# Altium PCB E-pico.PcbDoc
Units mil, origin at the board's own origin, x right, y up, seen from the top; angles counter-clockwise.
Board outline 2065 x 820 mil, 2 copper layers (Top Layer, Bottom Layer); 31 components, 39 nets, 175 pads, 130 vias.
Unrouted connection lines stored in the file: 26.
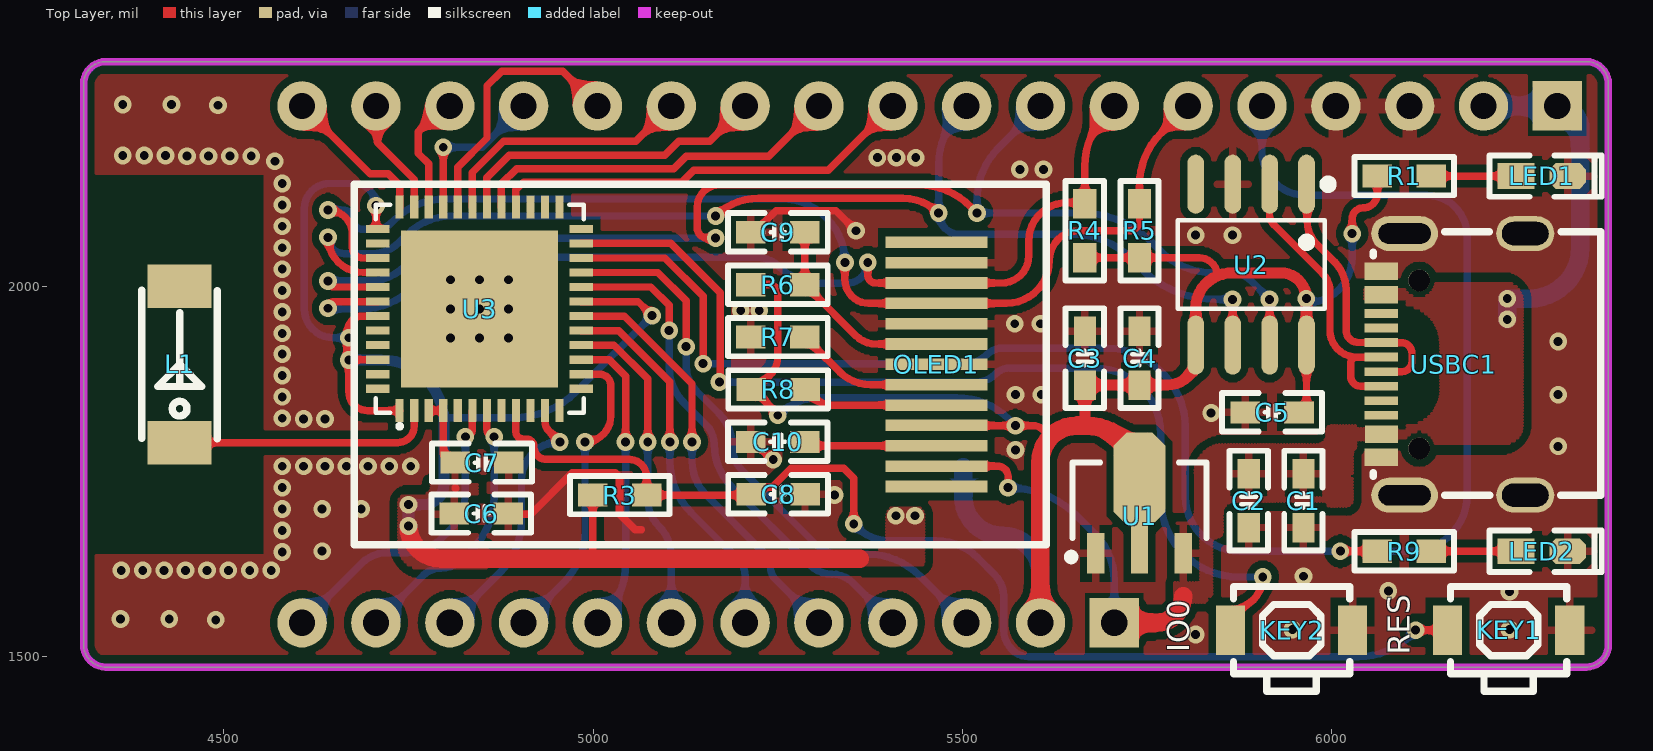
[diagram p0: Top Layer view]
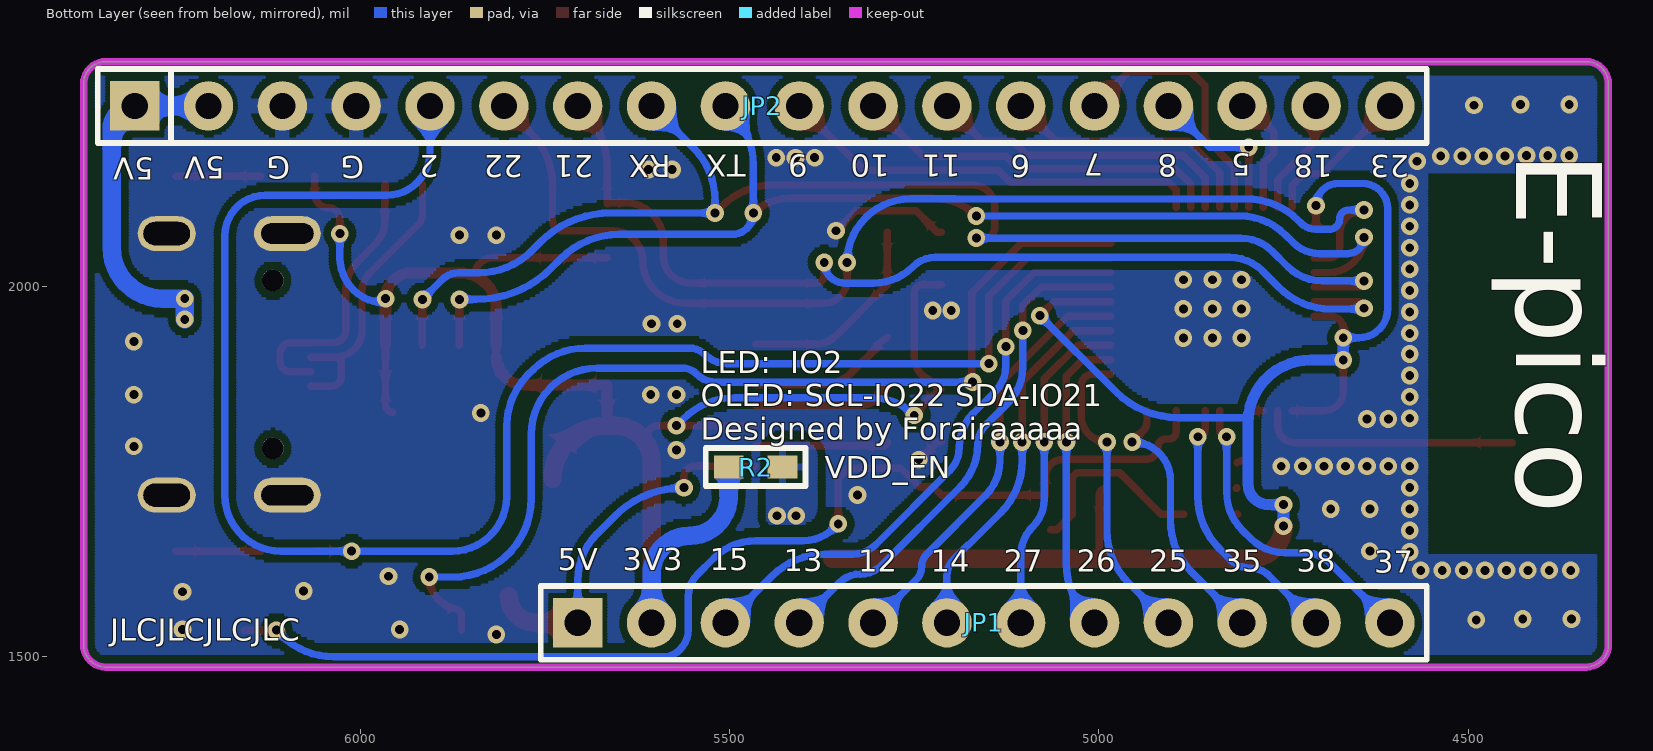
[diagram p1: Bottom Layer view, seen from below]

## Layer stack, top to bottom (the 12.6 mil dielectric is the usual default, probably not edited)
Top Solder: solder mask 0.4, Solder Resist, Dk 3.5
Top Layer: signal copper 1.4
Dielectric 1: dielectric 12.6, FR-4, Dk 4.8
Bottom Layer: signal copper 1.4
Bottom Solder: solder mask 0.4, Solder Resist, Dk 3.5

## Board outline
4310,1515 4310,2275 cw(c4340,2275) 4340,2305 6345,2305 cw(c6345,2275) 6375,2275 6375,1515 cw(c6345,1515) 6345,1485 4340,1485 cw(c4340,1515)

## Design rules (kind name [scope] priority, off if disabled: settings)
Clearance usbc [InNet('VBUS')] p1: gap=6 ignorepadtopadclearanceinfootprint=TRUE except(10: Arc-Fill Arc-Poly Arc-Region Track-Fill Track-Poly Track-Region SMDPad-Fill SMDPad-Poly SMDPad-Region Via-Fill Via-Poly Via-Region Fill-Fill Fill-Poly Fill-Region Poly-Poly Poly-Region Region-Region)
Clearance [All] p2: gap=6 ignorepadtopadclearanceinfootprint=TRUE except(10: Arc-Fill Arc-Poly Arc-Region Track-Fill Track-Poly Track-Region SMDPad-Fill SMDPad-Poly SMDPad-Region THPad-Fill THPad-Poly THPad-Region Via-Fill Via-Poly Via-Region Fill-Fill Fill-Poly Fill-Region Poly-Poly Poly-Region Region-Region)
PolygonConnect "for usbc" [HasFootprint('USB-C-SMD_16P')] p1: connectstyle=Direct reliefconductorwidth=20 reliefentries=4 polygonreliefangle="90 Angle" airgapwidth=10
PolygonConnect [All] p2: thpad.connectstyle=Relief thpad.reliefconductorwidth=20 thpad.reliefentries=4 thpad.polygonreliefangle="90 Angle" thpad.airgapwidth=10 smdpad.connectstyle=Relief smdpad.reliefconductorwidth=10 smdpad.reliefentries=4 smdpad.polygonreliefangle="90 Angle" smdpad.airgapwidth=10 via.connectstyle=Direct via.reliefconductorwidth=10 via.reliefentries=4 via.polygonreliefangle="90 Angle" via.airgapwidth=10
RoomDefinition E-pico [InComponentClass('E-pico')] p1: confinementstyle=ConfineIn formatcopy=TRUE lockcomponents=FALSE outline 0,0 2000,0 2000,1000 0,1000
RoutingVias [All] p1: holewidth=28 width=50 viastyle="Through Hole" minholewidth=28 minwidth=50 maxholewidth=28 maxwidth=50
SilkToSilkClearance [All] p1: silktosilkclearance=2
SilkToSolderMaskClearance [IsPad] p1: minsilkscreentomaskgap=2 clearancetoexposedcopper=TRUE
SolderMaskExpansion [All] p1: expansion=2.5 istentingtop=FALSE
Width [All] p1: maxlimit=100 minlimit=6 preferedwidth=10
28 further rules are at their usual default settings.

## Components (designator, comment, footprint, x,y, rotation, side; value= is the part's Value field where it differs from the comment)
C1 "10uf" C0603_M 5962,1710.5 r270 top locked
C2 "0.1uf" C0603_M 5888,1710.5 r270 top locked
C3 "10uf" C0603_M 5666,1903.5 r90 top locked
C4 "0.1uf" C0603_M 5740,1903.5 r90 top locked
C5 "104" C0603_M 5919.5,1830 r0 top locked
C6 "10uf" C0603_M 4848.5,1693 r180 top locked
C7 "0.1uf" C0603_M 4849.5,1762 r180 top locked
C8 "0.1uf" C0603_M 5250.5,1719 r180 top locked
C9 "10uf" C0603_M 5250.25,2074 r0 top locked
C10 "10uf" C0603_M 5250,1790 r0 top
JP1 "HDR-1X12" HDR2.54-LI-12P 5155.87,1545 r180 bottom locked
JP2 "HDR-1X18" HDR2.54-LI-18P 5455.87,2245 r180 bottom locked
KEY1 "Reset" SW-SMD_ST-1186S 6240,1535 r90 top locked
KEY2 "IO0" SW-SMD_ST-1186S 5946,1535 r90 top locked
L1 "AN2051-245" ANT2051 4440,1895 r90 top locked
LED1 "power" LED0603_Y 6285,2150 r0 top locked
LED2 "User" LED0603_Y 6285,1642 r0 top
OLED1 "OLED 12880" 0.78'OLED-12880-13pin-short 5465,1895 r90 top locked
R1 "10k" R0603_M 6098.5,2150 r0 top locked
R2 "0R" R0603_M 5465,1756 r180 bottom
R3 "10k" R0603_M 5036,1718 r0 top locked
R4 "10k" R0603_M 5666,2076 r90 top locked
R5 "10k" R0603_M 5740,2076 r90 top locked
R6 "10k" R0603_M 5250.25,2003 r0 top locked
R7 "560k" R0603_M 5250.25,1932 r0 top locked
R8 "4.7k" R0603_M 5250.5,1861 r0 top locked
R9 "10k" R0603_M 6098.5,1642 r0 top
U1 "LM1117F-3.3" SOT89-150P410X160-3N 5740,1710 r90 top locked
U2 "CH340N" SOP-8_L5.0-W4.0-P1.27-LS6.0-BL 5892,2030 r180 top locked
U3 "ESP32-PICO-D4" QFN-48_L7.0-W7.0-P0.50-BL-EP5.4 4846.27,1970.21 r0 top locked
USBC1 "TYPE-C 2.0 -16P" USB-C-SMD_16P 6165,1895 r270 top locked

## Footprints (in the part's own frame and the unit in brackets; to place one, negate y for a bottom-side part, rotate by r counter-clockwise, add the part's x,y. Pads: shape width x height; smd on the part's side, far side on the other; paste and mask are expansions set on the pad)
0.78'OLED-12880-13pin-short [mm]
  rect 0.4x3.5 smd: 1(-4.2,0) 1(-4.2,0) 2(-3.5,0) 3(-2.8,0) 4(-2.1,0) 5(-1.4,0) 6(-0.7,0) 7(0,0) 8(0.7,0) 9(1.4,0) 10(2.1,0) 11(2.8,0) 12(3.5,0) 13(4.2,0)
  silkscreen extent -6.2,-3.77 6.2,20.03
ANT2051 [mm]
  rect 1.5x2.2 smd: 1(-2.69,0) 2(2.69,0)
  silkscreen extent -2.56,-1.3 2.55,1.3, body extent -2.61,-1 2.59,1, height 1.2
C0603_M [mil] "贴片MLCC电容"
  rect 40x30 smd: 1(-36.5,0) 2(36.5,0)
  silkscreen extent -68,-26 68,26, body extent -31,-16 32,16, height 33
HDR2.54-LI-12P [mm] "排针，13脚"
  rect 1.7x1.7 hole 0.9: 1(-13.97,0)
  round 1.7 hole 0.9: 2(-11.43,0) 3(-8.89,0) 4(-6.35,0) 5(-3.81,0) 6(-1.27,0) 7(1.27,0) 8(3.81,0) 9(6.35,0) 10(8.89,0) 11(11.43,0) 12(13.97,0)
  silkscreen extent -15.24,-1.27 15.24,1.27, body extent -15.24,-1.27 15.24,1.27, height 2.54
HDR2.54-LI-18P [mm] "排针，18脚"
  rect 1.7x1.7 hole 0.9: 1(-21.59,0)
  round 1.7 hole 0.9: 2(-19.05,0) 3(-16.51,0) 4(-13.97,0) 5(-11.43,0) 6(-8.89,0) 7(-6.35,0) 8(-3.81,0) 9(-1.27,0) 10(1.27,0) 11(3.81,0) 12(6.35,0) 13(8.89,0) 14(11.43,0) 15(13.97,0) 16(16.51,0) 17(19.05,0) 18(21.59,0)
  silkscreen extent -22.86,-1.27 22.86,1.27, body extent -22.86,-1.27 22.86,1.27, height 2.54
LED0603_Y [mil] "黄色0603LED"
  rect 50x35 smd: 1(-35,0)
  oct 50x35 smd: 2(35,0)
  silkscreen extent -71,-28 81,28, body extent -32,-16 31,16, height 18
QFN-48_L7.0-W7.0-P0.50-BL-EP5.4 [mm]
  rect 0.28x0.8 smd: 1(-2.75,-3.5) 2(-2.25,-3.5) 3(-1.75,-3.5) 4(-1.25,-3.5) 5(-0.75,-3.5) 6(-0.25,-3.5) 7(0.25,-3.5) 8(0.75,-3.5) 9(1.25,-3.5) 10(1.75,-3.5) 11(2.25,-3.5) 12(2.75,-3.5) 25(2.75,3.5) 26(2.25,3.5) 27(1.75,3.5) 28(1.25,3.5) 29(0.75,3.5) 30(0.25,3.5) 31(-0.25,3.5) 32(-0.75,3.5) 33(-1.25,3.5) 34(-1.75,3.5) 35(-2.25,3.5) 36(-2.75,3.5)
  rect 0.8x0.28 smd: 13(3.5,-2.75) 14(3.5,-2.25) 15(3.5,-1.75) 16(3.5,-1.25) 17(3.5,-0.75) 18(3.5,-0.25) 19(3.5,0.25) 20(3.5,0.75) 21(3.5,1.25) 22(3.5,1.75) 23(3.5,2.25) 24(3.5,2.75) 37(-3.5,2.75) 38(-3.5,2.25) 39(-3.5,1.75) 40(-3.5,1.25) 41(-3.5,0.75) 42(-3.5,0.25) 43(-3.5,-0.25) 44(-3.5,-0.75) 45(-3.5,-1.25) 46(-3.5,-1.75) 47(-3.5,-2.25) 48(-3.5,-2.75)
  rect 5.4x5.4 smd: 49(0,0)
  silkscreen extent -3.58,-4.11 3.58,3.58, body extent -3.51,-3.51 3.51,3.51, height 0.9
R0603_M [mil] "1/10W贴片电阻"
  rect 40x31.5 smd: 1(-36.5,0) 2(36.5,0)
  silkscreen extent -68,-26 68,26, body extent -31,-16 32,16, height 16
SOP-8_L5.0-W4.0-P1.27-LS6.0-BL [mil]
  oval 22.6x80.14 smd: 1(-74.2,-108.97) 2(-24.2,-108.97) 3(25.8,-108.97) 4(75.8,-108.97) 5(75.8,108.97) 6(25.8,108.97) 7(-24.2,108.97) 8(-74.2,108.97)
  silkscreen extent -109,-115 100,60, body extent -99,-122 99,122, height 59
SOT89-150P410X160-3N [mm] "SOT89, 3-Leads, Body 4.50x2.45mm, Pitch 1.50mm, Lead Span 4.1mm, IPC Medium Density"
  rect 1.4x0.6 smd: 1(-1.8,1.5) 3(-1.8,-1.5)
  rect 1.8x0.6 smd: 2(-1.6,0)
  oct 3.175x1.778 smd: 2(0.762,0)
  silkscreen extent -2.05,-2.3 1.32,2.47, body extent -2.24,-2.15 1.86,2.15, height 1.61
SW-SMD_ST-1186S [mm]
  rect 1.7x1 smd: 1(0,2.1) 2(0,-2.1)
  silkscreen extent -2.1,-2 1.5,2, body extent -2.11,-2.51 1.49,2.49, height 1.55
USB-C-SMD_16P [mm] "封装库来自淘宝ID:黄晶宝石"
  oval 1.2x2 hole 0.8 slot 1.6 at 90 deg: 0(-4.5,2.475) 0(4.5,2.475)
  oval 1.2x2.3 hole 0.7 slot 1.8 at 90 deg: 0(-4.5,-1.675) 0(4.5,-1.675)
  rect 0.3x1.15 smd: A1(3.35,-2.473) A4(2.55,-2.471) A5(1.25,-2.475) A6(0.25,-2.475) A7(-0.25,-2.473) A9(-2.55,-2.475) A12(-3.35,-2.475) B1(-3.05,-2.475) B4(-2.25,-2.475) B5(-1.75,-2.475) B6(-0.75,-2.475) B7(0.75,-2.473) B9(2.25,-2.471) B12(3.05,-2.473)
  rect 0.3x1.148 smd: A8(1.75,-2.475) B8(-1.25,-2.475)
  round 0.75 hole 0.75 unplated: ""(-2.89,-1.175) ""(2.89,-1.175)
  silkscreen extent -4.56,-2.75 4.5,5.08, body extent -4.45,-2.87 4.49,5.03, height 3.25

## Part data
C1 C2 C3 C4 C5 C6 C7 C8 C9 C10: library part C, "贴片电容/MLCC电容"
JP1: library part "Header 12", "12P接插件"
JP2: library part "Header 18", "18P接插件"
KEY1 KEY2: library part 侧按小龟ST-1186S, "C589199"
LED1 LED2: library part LED-SMD, "贴片LED"
OLED1: library part 0.78寸12880oled
R1 R2 R3 R4 R5 R6 R7 R8 R9: library part R, "贴片电阻"
USBC1: library part USB2.0_Type-C_16Pin, "USB2.0_Type-C_16Pin母座"

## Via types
v1: diameter 24, hole 12, Top Layer to Bottom Layer, tented both sides, 121 vias
v2: diameter 24.02, hole 12, Top Layer to Bottom Layer, 9 vias

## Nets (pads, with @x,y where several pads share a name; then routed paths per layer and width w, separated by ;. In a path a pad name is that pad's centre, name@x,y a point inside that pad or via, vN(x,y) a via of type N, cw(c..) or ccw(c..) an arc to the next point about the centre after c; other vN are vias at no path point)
DN: U2.2 USBC1.A7 USBC1.B7 | length 399.8
  Top Layer w10: U2.2 5916,2138.76 5916,2098 ccw(c5935.31,2098) 5921.66,2084.34 5988,2018 cw(c5963.86,1993.86) 5998,1993.86 5998,1941 ccw(c6034.16,1941) 6034.16,1904.84 ; USBC1.B7 6039.53,1865.47 cw(c6039.53,1879) 6026,1879 6026,1896.69 cw(c6034.16,1896.69) 6034.16,1904.84 ; USBC1.A7 6034.16,1904.84
DP: U2.1 USBC1.A6 USBC1.B6 | length 408.7
  Top Layer w10: U2.1@5966.2,2113.22 U2.1 cw(c5964.28,2137.04) 5967,2137.04 5967,2089 ccw(c6010.46,2089) 5979.73,2058.27 6004,2034 cw(c5965.9,1995.9) 6019.78,1995.9 6019.78,1941.22 ccw(c6036.43,1941.22) 6036.43,1924.57 6067.53,1924.57 6094.47,1924.53 cw(c6094.47,1910) 6109,1910 6109,1899 cw(c6095.16,1899) 6095.16,1885.16 USBC1.A6
EN: C8.2 KEY1.1 R3.2 U3.9 | length 1551.2
  Top Layer w10: U3.9 4895.48,1803.52 ccw(c4905,1803.52) 4905,1794 4909,1794 cw(c4909,1783) 4920,1783 ccw(c4936.75,1783) 4936.75,1766.25 5048.75,1766.25 cw(c5048.75,1742.5) 5072.5,1742.5 R3.2 C8.2@5213,1718 ; C8.2 5224,1729 5242.73,1729 5267.97,1754.23 5339.6,1754.23 5353,1740.84 v1(5353,1679) ; v1(6114,1535) KEY1.1
  Bottom Layer w10: v1(5353,1679) 5358.55,1673.45 ccw(c5400.32,1715.23) 5400.32,1656.15 ; 5400.37,1656.15 5464.71,1656.15 cw(c5464.71,1576.13) 5521.29,1632.71 5544,1610 cw(c5515.03,1581.03) 5556,1581.03 5556,1536 ccw(c5594.63,1536) 5567.26,1508.74 5567.3,1508.7 cw(c5560.3,1501.56) 5567.37,1508.63 5567.93,1508.07 ccw(c5589.73,1529.73) 5589.73,1499 6036.58,1499 ccw(c6036.58,1599) 6107.29,1528.29 v1(6114,1535)
GND: C1.2 C2.2 C3.2 C4.2 C5.1 C6.1 C7.1 C8.1 C9.1 C10.1 JP2.3 JP2.4 KEY1.2 KEY2.2 LED1.2 LED2.2 OLED1.7 OLED1.9 OLED1.12 R7.1 U1.1 U2.3 U3.49 USBC1.0 USBC1.A1 USBC1.A12 USBC1.B1 USBC1.B12 | length 470.3
  Top Layer w10: C6.1@4885,1692 4915.81,1692 4971.81,1748 5030.14,1748 5036,1742.14 5036,1692 5057,1671 5065,1671 ; C10.1 5218.5,1790 5242.5,1766 v1(5244,1766) ; C9.1 5218.75,2074 5247.75,2103 5329,2103 v1(5356,2076)
  other v1: 5816,1529 5947,1536 6241,1536 4489,1549 4360,1550 4426,1550 6241,1587 6077,1588 5962,1608 4361,1616 4390,1616 4419,1616 4448,1616 4477,1616 4506,1616 4535,1616 4564,1616 4579,1641 4633,1642 4579,1670 4579,1699 4633,1699 4686,1699 5327,1718 4579,1728 4579,1757 4608,1757 4637,1757 4666,1757 4695,1757 4724,1757 4753,1757 5572,1779 6307,1784 4608,1821 4637,1821 4579,1822 5837,1829 4579,1851 5572,1854 5607,1854 6307,1854 4579,1880 4579,1909 6307,1926 4579,1937 5571,1950 5606,1950 4579,1966 5200,1968 5225,1968 4579,1995 4579,2024 4579,2053 5816,2070 5866,2070 4579,2082 4579,2111 4579,2140 5578,2159 5610,2159 4569,2170 5385,2175 5411,2175 5437,2175 4450,2177 4479,2177 4508,2177 4537,2177 4363,2178 4392,2178 4421,2178 4492,2246 4363,2247 4429,2247
  other v2: 4806.9,1930.84 4846.27,1930.84 4885.64,1930.84 4806.9,1970.22 4846.27,1970.22 4885.64,1970.22 4806.91,2009.59 4846.27,2009.59 4885.65,2009.59
IO0: KEY2.1 U3.23 | length 1370.7
  Top Layer w10: U3.23 5105.2,2058.8 5172,1992 5172,1873.41 cw(c5168.59,1873.41) v1(5171,1871) ; KEY2.1 5863.32,1554.26 5863.32,1557.46 5865.18,1560.07 cw(c5873.32,1554.26) 5871.43,1564.08 ccw(c5863.32,1607) v1(5907,1607)
  Bottom Layer w10: v1(5171,1871) 5518.44,1871 ccw(c5518.44,1908.56) 5545,1882 cw(c5564.31,1862.69) 5564.31,1890 5679.28,1890 cw(c5679.28,1800.49) 5768.79,1800.49 5768.79,1713.11 ccw(c5874.9,1713.11) 5874.9,1607 v1(5907,1607)
IO2: JP2.5 R9.1 U3.22 | length 2364
  Top Layer w10: U3.22 5097.22,2039.12 5149,1987.34 v1(5149,1896) ; v1(6012,1642) R9.1
  Bottom Layer w10: v1(5149,1896) 5504.03,1896 ccw(c5504.03,1936.97) 5533,1908 cw(c5554.73,1886.27) 5554.73,1917 5695.58,1917 cw(c5695.58,1817) 5766.29,1887.71 cw(c5699.43,1809.75) 5802.14,1809.75 5802.14,1715.86 ccw(c5876,1715.86) 5876,1642 v1(6012,1642) 6107.87,1642 ccw(c6107.87,1717.84) 6183.71,1717.84 6183.71,2069.29 ccw(c6129,2069.29) 6129,2124 5965,2124 cw(c5965,2183.13) 5905.87,2183.13 JP2.5
IO5: JP2.16 U3.34 | length 187.1
  Top Layer w10: U3.34 4777.37,2166.63 4763.34,2180.66 4763.34,2210.34 4798,2245 JP2.16 JP2.16@4805.87,2233.47
  Bottom Layer w10: JP2.16@4795.34,2245 JP2.16
IO6: JP2.13 U3.31 | length 353.6
  Top Layer w10: U3.31 4836.43,2154.86 4878.57,2197 5057.87,2197 JP2.13
IO7: JP2.14 U3.32 | length 357.8
  Top Layer w10: U3.32 4816.74,2162.06 4856.3,2201.62 4856.3,2272.12 4876.18,2292 4958.87,2292 JP2.14
IO8: JP2.15 U3.33 | length 228.2
  Top Layer w10: U3.33@4797.03,2108.03 v1(4797,2189) ; JP2.15@4890.33,2244.55 JP2.15@4905.43,2244.55
  Bottom Layer w10: v1(4797,2189) 4849.87,2189 JP2.15
IO9: JP2.10 U3.28 | length 580.8
  Top Layer w10: U3.28 4895.48,2131.29 4905.8,2141.62 5120.28,2141.62 5136.5,2157.83 5318.7,2157.83 5355.87,2195 JP2.10
IO10: JP2.11 U3.29 | length 505.2
  Top Layer w10: U3.29 4875.8,2139.43 4896.36,2159.99 5109,2159.99 5126.01,2177 5237.87,2177 JP2.11
IO11: JP2.12 U3.30 | length 429.9
  Top Layer w10: U3.30 4856.11,2147.91 4886.2,2178 5097.12,2178 5116.12,2197 5157.87,2197 JP2.12
IO12: JP1.5 U3.18 | length 577.9
  Top Layer w10: U3.18 5042.44,1960.38 5134,1868.82 v1(5134,1790)
  Bottom Layer w10: v1(5134,1790) 5134,1764.47 ccw(c5199.72,1764.47) 5153.25,1718 5232.69,1638.56 cw(c5215.25,1621) 5240,1621.03 ccw(c5264.45,1621) 5247.2,1603.67 JP1.5
IO13: JP1.4 U3.20 | length 692.9
  Top Layer w10: U3.20 5078.25,1999.75 5103,1975 v1(5103,1941)
  Bottom Layer w10: v1(5103,1941) 5103,1891.28 ccw(c5171.28,1891.28) 5123,1843 5153.39,1812.61 cw(c5127.79,1787) 5164,1787 ccw(c5246.08,1787) 5188.04,1728.96 5293.93,1623.07 ccw(c5323,1652.04) 5323,1611 cw(c5323,1570.26) 5351.83,1599.04 5351.87,1599 JP1.4
IO14: JP1.6 U3.17 | length 512.1
  Top Layer w10: U3.17 5034.97,1940.69 5104,1871.66 v1(5104,1790)
  Bottom Layer w10: v1(5104,1790) 5104,1764.42 ccw(c5204,1764.42) 5133.29,1693.71 5176.58,1650.42 cw(c5176.58,1648) 5178.29,1649.71 5196,1632 cw(c5172.16,1608.16) 5205.87,1608.16 JP1.6
IO15: JP1.3 U3.21 | length 814.1
  Top Layer w10: U3.21 5087.7,2019.43 5126,1981.13 v1(5126,1919)
  Bottom Layer w10: v1(5126,1919) 5126,1892.8 ccw(c5173.8,1892.8) 5140,1859 5169.91,1829.09 cw(c5123.82,1783) 5189,1783 ccw(c5234.87,1783) 5202.44,1750.56 5301.94,1651.06 ccw(c5333.38,1682.38) 5333.45,1638 5371.45,1638 cw(c5371.45,1538) 5442.16,1608.71 JP1.3 cw(c5505.87,1568.59) JP1.3@5489.2,1551.9
IO18: JP2.17 U3.35 | length 158.5
  Top Layer w10: JP2.17 4708,2242.87 4708,2195 4757.69,2145.31 U3.35
IO21: JP2.7 OLED1.11 R4.2 U3.42 | length 1384.6
  Top Layer w10: v1(4641,1971) cw(c4650.06,1971) 4650.06,1980.06 U3.42 ; v1(5372,2033) 5372,2016 ccw(c5382.76,2016) 5382.76,2005.24 5553.24,2005.24 ccw(c5553.24,2042) 5590,2042 5590,2062 cw(c5642,2062) 5642,2114 5664.5,2114 cw(c5664.5,2112.5) R4.2 5666,2163.71 cw(c5766,2163.71) 5695.29,2234.42 JP2.7
  Bottom Layer w10: v1(4641,1971) ccw(c4643.41,1973.41) 4643.41,1970 4685.58,1970 ccw(c4685.58,2070) 4756.29,1999.29 4778.62,2021.62 cw(c4823,1977.23) 4823,2040 5221.37,2040 cw(c5221.37,1997.1) 5251.75,2027.38 ccw(c5305.79,2081.42) 5305.79,2005 5344,2005 ccw(c5344,2033) v1(5372,2033)
IO22: JP2.6 OLED1.10 R5.2 U3.39 | length 1570.3
  Top Layer w10: v1(4641,2104) cw(c4641,2071) 4674,2071 4674,2053 ccw(c4687.88,2053) 4687.88,2039.12 U3.39 ; v1(5341,2033) 5341,2010 ccw(c5373.32,2010) 5373.32,1977.68 OLED1.10 5559.68,1977.68 ccw(c5559.68,2036) 5618,2036 cw(c5658,2036) 5658,2076 5726,2076 ccw(c5726,2090) 5740,2090 R5.2 5740,2137.71 cw(c5840,2137.71) 5769.29,2208.42 JP2.6
  Bottom Layer w10: v1(4641,2104) 4662,2104 cw(c4662,2092) 4674,2092 ccw(c4688,2092) 4688,2078 4706.69,2078 ccw(c4706.69,2105.31) 4725.99,2085.99 4729.71,2089.71 cw(c4800.42,2019) 4800.42,2119 4813,2119 5195.37,2119.09 5254.91,2119.09 cw(c5254.91,2033) v1(5341,2033)
IO23: JP2.18 U3.36 | length 206.1
  Top Layer w10: JP2.18 4697.87,2153 4722.4,2153 4738,2137.4 U3.36
IO25: JP1.9 U3.14 | length 420
  Top Layer w10: U3.14 5008.36,1881.64 cw(c5008.36,1866) 5024,1866 5024,1825 cw(c4989,1825) v1(4989,1790)
  Bottom Layer w10: JP1.9 4959.71,1598.84 ccw(c4889,1669.55) 4989,1669.55 v1(4989,1790)
IO26: JP1.8 U3.15 | length 414.7
  Top Layer w10: U3.15 5021.68,1901.32 5044,1879 v1(5044,1790)
  Bottom Layer w10: JP1.8 5014.71,1553.84 ccw(c4944,1624.55) 5044,1624.55 v1(5044,1790)
IO27: JP1.7 U3.16 | length 447.7
  Top Layer w10: U3.16 5028.32,1921.01 5074,1875.32 v1(5074,1790)
  Bottom Layer w10: v1(5074,1790) 5074,1712.21 ccw(c5125.21,1712.21) 5089,1676 cw(c5048.26,1635.26) 5105.87,1635.26 JP1.7
IO35: JP1.10 U3.11 | length 374.5
  Top Layer w10: U3.11 4934.85,1817.25 ccw(c4951.99,1817.25) 4939.87,1805.13 v1(4955,1790)
  Bottom Layer w10: JP1.10@4805.87,1558.87 JP1.10 4873.71,1612.84 ccw(c4803,1683.55) 4903,1683.55 4903,1738 cw(c4955,1738) v1(4955,1790)
IO37: JP1.12 U3.6 | length 419.8
  Top Layer w10: v1(4827,1797) ccw(c4827,1806.43) 4836.43,1806.43 U3.6
  Bottom Layer w10: JP1.12 4685.93,1625.06 cw(c4722,1589) 4722,1640 4748.53,1640 ccw(c4748.53,1704.31) 4794,1658.83 4805.67,1670.5 ccw(c4754.17,1722) 4827,1722 v1(4827,1797)
IO38: JP1.11 U3.7 | length 369.8
  Top Layer w10: U3.7 4856.11,1806.89 ccw(c4866,1806.89) v1(4866,1797)
  Bottom Layer w10: JP1.11 4769.88,1609.01 cw(c4794,1584.9) 4794,1619 ccw(c4794,1658.83) 4822.17,1630.67 4836.71,1645.21 ccw(c4766,1715.92) 4866,1715.92 v1(4866,1797)
NetC9_2: C9.2 OLED1.8 R6.2 | length 280.9
  Top Layer w10: C9.2 R6.2 5297.5,1992.25 5355.95,1933.8 ccw(c5383.02,1960.77) 5383.04,1922.56 ; 5383.08,1922.56 OLED1.8
NetC10_2: C10.2 OLED1.3 | length 181.5
  Top Layer w10: C10.2 ccw(c5291.74,1790) 5291.74,1784.76 OLED1.3
NetL1_1: L1.1 U3.2 | length 351.5
  Top Layer w10: L1.1 4735.48,1789.09 ccw(c4735.48,1811.31) 4757.69,1811.31 U3.2
NetLED1_1: LED1.1 R1.2 | length 115
  Top Layer w10: R1.2 LED1.1
NetLED2_1: LED2.1 R9.2 | length 115
  Top Layer w10: R9.2 LED2.1
NetOLED1_5: OLED1.5 R8.2 | length 187.3
  Top Layer w10: R8.2 5292.9,1861 5295.1,1859.83 cw(c5290.41,1851) 5299.87,1854.25 ccw(c5319.88,1861) 5319.88,1839.88 OLED1.5
NetOLED1_6: OLED1.6 R7.2 | length 203.7
  Top Layer w10: R7.2 5301.01,1921.25 5301.01,1917.74 5333.95,1884.8 cw(c5326.88,1877.73) 5334.03,1884.72 ccw(c5375.79,1926.54) 5375.81,1867.44 ; 5375.85,1867.44 OLED1.6
USB-UART_RX: JP2.8 U2.7 U3.41 | length 1755.8
  Top Layer w10: v1(4641,2008) ccw(c4649.25,2008) 4649.25,1999.75 U3.41 ; v1(5166,2066) 5155,2066 cw(c5155,2080) 5141,2080 5141,2108 cw(c5171,2108) 5171,2138 5440.58,2138 cw(c5440.58,2038) 5511.29,2108.71 v1(5520,2100) ; v1(5916,1983) 5916.2,1983 U2.7
  Bottom Layer w10: v1(4641,2008) 4697.35,2008 ccw(c4697.35,2074.75) 4744.55,2027.55 4765.4,2048.4 cw(c4807.89,2005.91) 4807.89,2066 v1(5166,2066) ; JP2.8 5549.29,2188.42 ccw(c5620,2117.71) 5520,2117.71 v1(5520,2100) 5661,2100 cw(c5661,1964.8) 5756.62,2060.38 ; 5756.65,2060.35 5768.71,2048.29 ccw(c5839.42,2119) 5839.42,2019 5867.37,2019 cw(c5867.37,1988.52) 5888.93,2010.07 v1(5916,1983)
USB-UART_TX: JP2.9 U2.6 U3.40 | length 1619.6
  Top Layer w10: v1(4641,2067) ccw(c4688.57,2067) 4688.57,2019.43 U3.40 ; v1(5166,2096) cw(c5223.94,2038.06) 5223.94,2120 5419.72,2120 cw(c5419.72,2051.72) v1(5468,2100) ; v1(5866,1983) 5866.2,1983 U2.6
  Bottom Layer w10: v1(4641,2067) ccw(c4662.94,2067) 4662.94,2045.06 4700.88,2045.06 ccw(c4700.93,2096.07) 4737,2060 4747.1,2070.1 cw(c4809.63,2007.57) 4809.63,2096 v1(5166,2096) ; JP2.9 5497.29,2236.42 ccw(c5568,2165.71) 5468,2165.71 v1(5468,2100) ccw(c5497,2100) 5497,2071 5649.58,2071 cw(c5649.58,1958.93) 5728.82,2038.17 5741.99,2025.01 ccw(c5843.4,2126.4) 5843.42,1983 ; 5843.46,1983 v1(5866,1983)
VBUS: C1.1 C2.1 JP1.1 JP2.1 JP2.2 OLED1.2 U1.3 USBC1.A4 USBC1.A9 USBC1.B4 USBC1.B9 | length 975.4
  Top Layer w10: OLED1.2 5547.8,1757.2 cw(c5547.8,1743) 5562,1743 v1(5562,1728) ; U1.3@5799,1639.13 U1.3
  Top Layer w25: JP1.1 5763,1545 ccw(c5763,1581) 5799,1581
  Bottom Layer w10: v1(5562,1728) cw(c5562,1594.59) 5656.41,1688.85 5679.58,1665.69 cw(c5672.51,1658.61) 5679.65,1665.61 ; 5679.68,1665.58 cw(c5616.32,1602.29) 5705.87,1602.29 JP1.1
  Bottom Layer w25: JP2.2 JP2.1 cw(c6305.87,2213.87) 6337,2213.87 6337,2053 cw(c6268,2053) 6268,1984 v1(6238,1984) v1(6238,1956)
VCC_3V3: C3.1 C4.1 C5.2 JP1.2 OLED1.4 R1.1 R2.1 R4.1 R5.1 R6.1 R8.1 U1.2 U2.5 U2.8 | length 2525.7
  Top Layer w10: R6.1 5239,2003 cw(c5239,1991.75) 5250.25,1991.75 5250.25,1906 cw(c5214,1906) 5228.73,1872.88 5228.73,1871.75 R8.1 5229,1850.25 v1(5250,1826) ; OLED1.4 5465,1812 v1(5572,1812) 5595.69,1812 cw(c5595.69,1792.14) 5615.55,1792.14 ; 5655,1812 ccw(c5655,1823) 5666,1823 ; 5666,1814 ccw(c5668,1814) 5668,1812 ; R4.1 R5.1 5820.75,2039.5 cw(c5820.75,2014.73) 5845.51,2014.73 ; U2.5@5816.2,1893.2 5816.2,1905.2 U2.5 ; C5.2 ccw(c5956,1840.2) 5966.2,1840.2 5966.2,1868 U2.8 ; v1(5966,1984) v1@5966.2,1984 ; v1(6028,2072) 6028,2092 cw(c6043,2092) 6043,2107 ccw(c6043,2126) 6062,2126 R1.1
  Top Layer w15: 5666,1823 C3.1 C4.1 5778,1867 ccw(c5778,1905.2) U2.5@5816.2,1905.2 ; U2.5 5816.2,1971.2 cw(c5863.18,1971.2) 5845.51,2014.73 cw(c5867.37,1960.88) 5867.37,2019 5931,2019 cw(c5931,1984) v1(5966,1984) ; U2.8 v1@5966.2,1984
  Top Layer w25: JP1.2 5605.87,1762.87 cw(c5655,1762.87) 5615.55,1792.14 cw(c5655,1762.87) 5655,1812 5668,1812 cw(c5668,1740) U1.2@5740,1740
  Bottom Layer w10: v1(5250,1826) cw(c5307.94,1768.06) 5307.94,1850 5492.58,1850 cw(c5492.58,1750) 5563.29,1820.71 v1(5572,1812) ; v1@5966,1978 ccw(c5966,2040) 6028,2040 v1(6028,2072)
  Bottom Layer w25: R2.1 5501.5,1715.5 ccw(c5554,1715.5) 5554,1663 cw(c5554,1611.13) 5605.87,1611.13 JP1.2
VDD: C6.2 C7.2 R2.2 R3.1 U3.1 U3.3 U3.4 U3.19 U3.37 U3.43 U3.46 | length 2306.1
  Top Layer w10: v1(4669,1901) 4669,1858 ccw(c4694.59,1858) 4694.59,1832.41 U3.1 ; v1@4669,1901.32 U3.46 ; v1(4669,1931) 4669,1943 cw(c4686.38,1943) 4686.38,1960.38 U3.43 ; v1(4706,2110) 4706,2080.96 ccw(c4708.47,2080.96) U3.37 ; U3.3 U3.4 4797.06,1821.67 4797.06,1775.44 ccw(c4808.73,1775.44) 4798.65,1769.55 4801.4,1766.8 4801.66,1766.7 4803.24,1766.04 C7.2 ; C6.2@4812,1692 ccw(c4812,1693) C6.2@4813,1693 ; 4813,1728 ccw(c4814,1728) 4814,1727 ; U3.19 5060.87,1980.06 5079.93,1961 v1(5080,1961) ; R3.1@4990.5,1727 cw(c4990.5,1718) R3.1 4999.5,1637.5 cw(c4994,1637.5) 4994,1632
  Top Layer w15: v1@4669,1901.32 v1(4669,1931)
  Top Layer w25: v1(4750,1676) ccw(c4794,1676) 4794,1632 4994,1632 5361,1632
  Bottom Layer w10: v1(4669,1931) 4648,1931 cw(c4648,1970) 4609,1970 4609,2106 cw(c4643,2106) 4643,2140 4676,2140 cw(c4676,2110) v1(4706,2110) ; 4797.48,1822.93 4892.49,1822.93 ccw(c4892.49,1942.27) 4976.88,1857.88 v1(5080,1961) ; R2.2@5428,1756 R2.2
  Bottom Layer w15: v1(4669,1931) v1(4669,1901) 4713,1901 cw(c4713,1816) 4797.06,1828.59 cw(c4713,1816) 4798,1816 4798,1733 cw(c4770,1733) 4770,1705 v1(4750,1705) v1(4750,1676)
  other v1: 5410,1690 5436,1690
pads on no net: L1.2 OLED1.1 OLED1.13 U2.4 U3.5 U3.8 U3.10 U3.12 U3.13 U3.24 U3.25 U3.26 U3.27 U3.38 U3.44 U3.45 U3.47 U3.48 USBC1. USBC1.A5 USBC1.A8 USBC1.B5 USBC1.B8

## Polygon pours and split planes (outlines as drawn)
GND on Top Layer "GND_L01_P034" (hatched Horizontal grid 2 track 5, remove dead copper, pour order 34): 4556,2154 4310,2154 4310,2305 6375,2305 6375,1486 6374,1485 4310,1485 4310,1638 4556,1638
VBUS on Top Layer "VBUS_L01_P002" (hatched 90Degree grid 4 track 5, remove dead copper, pour order 2): 6000,1812 ccw(c6000,1806) 5994,1806 5994,1800 cw(c5980,1800) 5980,1786 5849,1786 ccw(c5853.49,1748.5) 5816,1744 5816,1697 cw(c5800,1697) 5800,1681 5793,1681 ccw(c5795.49,1673.5) 5788,1671 5788,1578.99 ccw(c5793.3,1578.33) 5793,1573 5829,1573 ccw(c5830.53,1580.45) 5837.99,1578.99 5838,1655 cw(c5843,1655) 5843,1660 ccw(c5843,1669) 5852,1669 5852,1693 cw(c5869,1693) 5869,1710 5990,1710 cw(c5990.4,1705.4) 5995,1705 ccw(c5997.5,1705.5) 5998,1703 6019,1703 ccw(c6020,1711) 6028,1710 6028,1774 cw(c6042.5,1771.5) 6045,1786 6092,1786 6092,1812
VDD on Top Layer "VDD_L01_P018" (hatched Horizontal grid 4 track 5, remove dead copper, pour order 18): 4737,1708 cw(c4747,1708) 4747,1718 4769,1718 ccw(c4769,1730) 4781,1730 4781,1735 cw(c4795,1735) 4795,1749 4831,1749 cw(c4831,1737) 4843,1737 4843,1655 ccw(c4850,1655) 4850,1648 cw(c4850,1640) 4858,1640 4858,1626 cw(c4850,1626) 4850,1618 4769,1618 cw(c4768.5,1649.5) 4737,1649
VDD on Top Layer "VDD_L01_P013" (hatched Horizontal grid 4 track 5, remove dead copper, pour order 13): 5410,1702 5436,1702 cw(c5436,1690) 5448,1690 5448,1629 cw(c5439,1629) 5439,1620 5368,1620 cw(c5368,1627) 5361,1627 5361,1637 cw(c5367,1637) 5367,1643 5384,1643 ccw(c5382.84,1658.16) 5398.02,1659 5398.02,1689.23 cw(c5410,1690)
VBUS on Top Layer "VBUS_L01_P000" (hatched Horizontal grid 4 track 5, remove dead copper, pour order 0): 6045,1975 6096,1975 cw(c6096,1923) 6148,1923 6148,1860 cw(c6100,1860) 6100,1812 6045,1812 6045,1786 6232,1786 ccw(c6230.25,1814.25) 6258.5,1816 6258.5,1980.5 ccw(c6232,1980.5) 6232,2007 6045,2007
GND on Bottom Layer "GND_L02_P037" (hatched Horizontal grid 4 track 5, remove dead copper, pour order 37): 4310,1638 4556,1638 4556,2154 4310,2154 4310,2305 6375,2305 6375,2258 6375,2257 6375,2256 6375,1486 6374,1485 4310,1485
VDD on Bottom Layer "VDD_L02_P008" (hatched Horizontal grid 4 track 5, remove dead copper, pour order 8): 5449,1686 cw(c5442,1686) 5442,1679 5405,1679 cw(c5405,1701) 5383,1701 5383,1771 cw(c5402,1771) 5402,1790 5434,1790 cw(c5434,1775) 5449,1775 5449,1771

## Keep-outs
Keep-Out Layer:
  the board outline again, w10

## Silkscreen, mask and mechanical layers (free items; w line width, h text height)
Top Overlay:
  text "IO0" at 5807.15,1505 h30 r90
  text "RES" at 6106,1502 h30 r90
Bottom Overlay:
  text "E-pico" at 4473.12,2182.77 h200 r90
  text "5" at 4794,2180 h30 r180
  text "7" at 4994,2180 h30 r180
  text "8" at 4894,2179 h30 r180
  text "11" at 5187,2179 h30 r180
  text "10" at 5283,2179 h30 r180
  text "9" at 5394,2179 h30 r180
  text "TX" at 5478,2179 h30 r180
  text "23" at 4580,2178 h30 r180
  text "18" at 4683,2178 h30 r180
  text "6" at 5093,2178 h30 r180
  text "RX" at 5580,2178 h30 r180
  text "21" at 5685,2178 h30 r180
  text "22" at 5780,2178 h30 r180
  text "2" at 5894,2178 h30 r180
  text "G" at 5995,2177 h30 r180
  text "G" at 6095,2176 h30 r180
  text "5V" at 6184,2176 h30 r180
  text "5V" at 6280,2175 h30 r180
  text "LED:  IO2 / OLED: SCL-IO22 SDA-IO21 / Designed by Forairaaaaa" at 5539,1793 h30
  text "VDD_EN" at 5371,1741 h30
  text "15" at 5527,1616 h30
  text "3V3" at 5645,1616 h30
  text "5V" at 5733,1616 h30
  text "13" at 5427,1615 h30
  text "38" at 4732,1614 h30
  text "35" at 4832,1614 h30
  text "25" at 4932,1614 h30
  text "26" at 5030,1614 h30
  text "27" at 5129,1614 h30
  text "14" at 5228,1614 h30
  text "12" at 5326,1614 h30
  text "37" at 4627,1613 h30
  text "JLCJLCJLCJLC" at 6339,1521 h30
Mechanical 1:
  the board outline again, w10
